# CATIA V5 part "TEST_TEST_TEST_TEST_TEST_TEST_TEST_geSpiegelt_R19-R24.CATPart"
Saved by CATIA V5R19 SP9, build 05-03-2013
Part number: Part_gespiegelt
Bounding box of the stored display mesh (mm): x -32.796 to 15.753, y -87.959 to 87.959, z 0 to 40
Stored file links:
  L:\pool\2209\09_Prüfungen-Kinematik-Gewicht\TEST_TEST_TEST_TEST_TEST_TEST_TEST_geSpiegelt_R19-R24.CATPart
  L:\pool\2209\09_Prüfungen-Kinematik-Gewicht\TEST_TEST_TEST_TEST_TEST_TEST_TEST_Spiegelung_R19-R24.CATPart
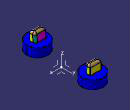
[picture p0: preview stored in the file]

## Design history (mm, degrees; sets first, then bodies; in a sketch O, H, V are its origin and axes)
AxisSystem1: origin (0, 0, 0), X (1, 0, 0), Y (0, 1, 0), Z (0, 0, 1)
Body1 (main body)
Body2
  Solid1: linked copy from another document
  Mirror1: of the body so far, about ZX plane of AxisSystem1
